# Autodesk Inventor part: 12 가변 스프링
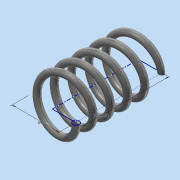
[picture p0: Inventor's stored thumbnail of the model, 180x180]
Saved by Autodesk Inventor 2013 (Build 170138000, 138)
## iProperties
Created: 2015-02
Part Number: 12 가변 스프링
Material: 강철, 탄소
Document SubType Name: Modeling
Designer: WINDOWS7
Density: 7.87 g/cm^3
Mass: 18.9518 g
Surface Area: 32.5528 cm^2
Volume: 2.40811 cm^3
Author: WINDOWS7
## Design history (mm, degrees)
sketch "스케치1"
  geometry: L1 (0, 0)-(11, 0); L2 (11, 0)-(11, 40.095); L3 (11, 40.095)-(0, 40.095); L4 (0, 40.095)-(0, 0); C1 r 1.5 at (11, 0)
  constraints: 8 end point, 2 parallel, 1 centre point, 1 coincident, 1 horizontal, 1 perpendicular
  dimensions: "d0" = 22 diameter of L2 L4; "d2" = 40.0955 distance of L1.end L2.end (derived); "d3" = 3 diameter of C1
feature "코일1" sketch "스케치1" pitch "d4" = 10; turns "d6" = 5; dims "d5" = 40.0955 (= d2), "d7" = 0, angle "d8" = 90 deg, angle "d9" = 90 deg, "d10" = 0, "d11" = 0
feature "분할1"
node "작업 평면1"
feature "분할2"
node "솔리드1"
other parameters: "d12" = 90 deg
